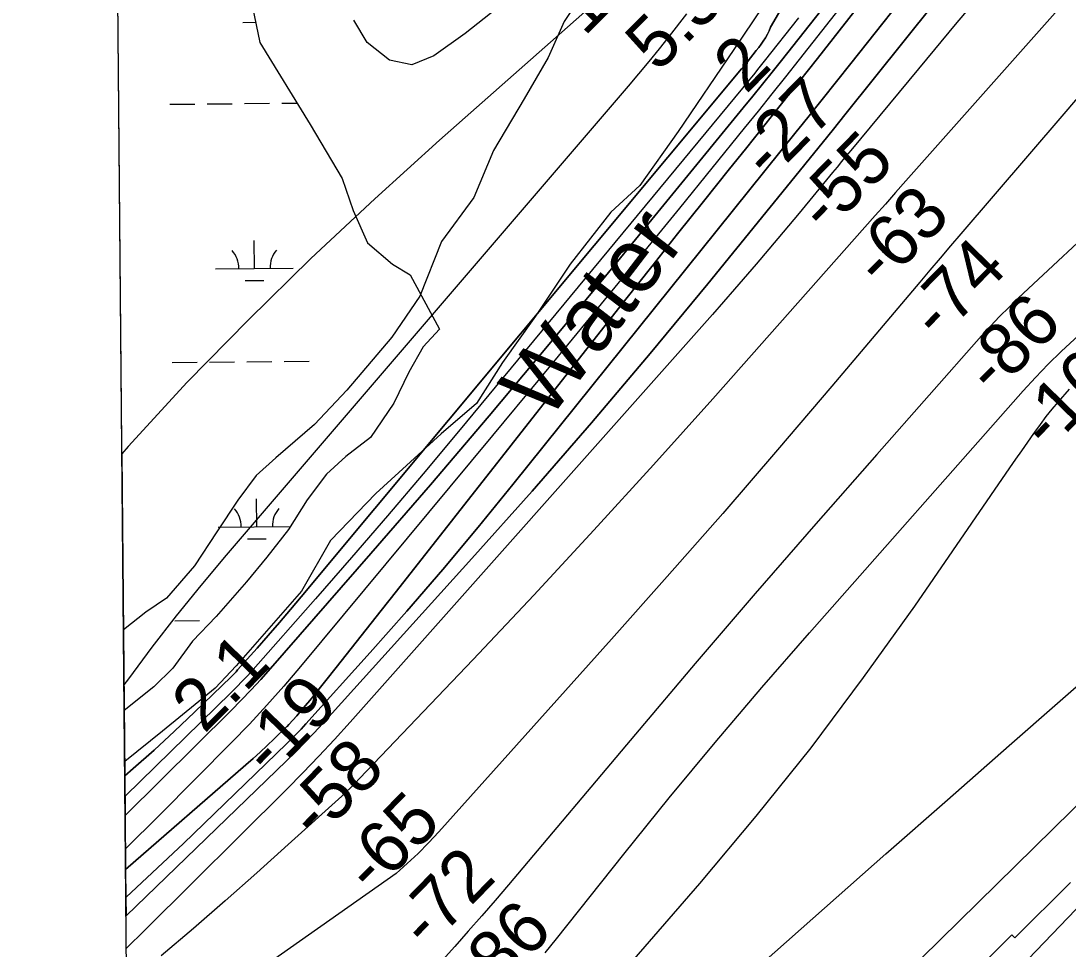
# Model space of a CAD drawing. Extents: x 3598634 to 3636690, y 517270 to 542944.
# Drawn here: x 3602690 to 3604038, y 525564 to 526759 of the extents above; entities that cross this region are included whole.
import ezdxf

# ---------------------------------------------------------------- set-up
doc = ezdxf.new("R2010")
doc.units = 0
for name, color, linetype in [('V-GRID-FRAM', 7, 'Continuous'), ('V-RIVR-EDGE', 7, 'Continuous'), ('V-RIVR-IDEN', 7, 'Continuous'), ('V-RIVR-RANG', 7, 'Continuous'), ('V-RRAP-RVMT', 7, 'Continuous'), ('V-SITE-VEGE', 7, 'Continuous'), ('V-TOPO-DPTH', 7, 'Continuous'), ('V-TOPO-MAJR', 7, 'Continuous'), ('V-TOPO-MINR', 7, 'Continuous'), ('V-TOPO-WATR', 7, 'Continuous'), ('V-WETL-SWMP', 7, 'Continuous')]:
    doc.layers.add(name, color=color, linetype=linetype)

msp = doc.modelspace()

# ---------------------------------------------------------------- linework, layer by layer
at = {"layer": 'V-GRID-FRAM'}
msp.add_lwpolyline([(3602690.3, 540859.2), (3634347.4, 541153.9), (3634524.6, 522971.8), (3602851.6, 522676.9), (3602690.3, 540859.2)], dxfattribs=at)
at = {"layer": 'V-RIVR-EDGE'}
msp.add_lwpolyline([(3603689.5, 526840.5), (3603658.1, 526797), (3603608.3, 526722.4), (3603536.4, 526617.2), (3603487.2, 526547.5), (3603449.7, 526513.3), (3603397.5, 526446), (3603352.6, 526379.3), (3603310.1, 526319.4), (3603276.9, 526266.8), (3603231.5, 526227.7), (3603147.4, 526150.7), (3603089, 526090.1), (3603051.5, 526024.7), (3602967.3, 525928.7), (3602940.2, 525900), (3602872.7, 525844.4), (3602823.9, 525805.3)], dxfattribs=at)
at = {"layer": 'V-RRAP-RVMT'}
for p, q in [((3604041.5, 525649.8), (3603970.1, 525578.4)), ((3603966.1, 525582.3), (3603878.4, 525494.7)), ((3603970.1, 525578.4), (3603966.1, 525582.3))]:
    msp.add_line(p, q, dxfattribs=at)
at = {"layer": 'V-SITE-VEGE'}
for p, q in [((3602822.4, 525975.2), (3602813.5, 526979.6)), ((3603424.1, 526810.7), (3603389.8, 526758.5)), ((3603389.8, 526758.5), (3603369.3, 526712.1)), ((3603369.3, 526712.1), (3603338.2, 526659.2)), ((3603338.2, 526659.2), (3603298.9, 526592.4)), ((3603298.9, 526592.4), (3603273.5, 526532.1)), ((3603273.5, 526532.1), (3603231.8, 526475.1)), ((3603231.8, 526475.1), (3603204, 526405)), ((3603204, 526405), (3603168, 526352.1)), ((3603168, 526352.1), (3603109.9, 526283.7)), ((3603109.9, 526283.7), (3603068.3, 526239.8)), ((3603068.3, 526239.8), (3603018.5, 526196.7)), ((3603018.5, 526196.7), (3602993.1, 526173.9)), ((3602993.1, 526173.9), (3602969.4, 526142.1)), ((3602969.4, 526142.1), (3602942.4, 526101.4)), ((3602942.4, 526101.4), (3602913.8, 526057.4)), ((3602913.8, 526057.4), (3602877.8, 526015.9)), ((3602877.8, 526015.9), (3602850.9, 525998)), ((3602850.9, 525998), (3602822.4, 525975.2))]:
    msp.add_line(p, q, dxfattribs=at)
at = {"layer": 'V-TOPO-DPTH'}
for points in [[(3604119.6, 527546.6), (3603655.5, 526751.3), (3603653.6, 526746.6), (3603651.3, 526742.2), (3603648.8, 526737.8), (3603646.1, 526733.5), (3603643.2, 526729.3), (3603640.2, 526725.2), (3603637.1, 526721.2), (3603625.4, 526706.4), (3603623.6, 526704.2), (3603621.8, 526702), (3603620, 526699.8), (3603618.2, 526697.7), (3603051.3, 526017.8), (3603037.2, 526001.1), (3603023, 525984.4), (3603008.7, 525967.9), (3602994.3, 525951.5), (3602969.3, 525923.4), (3602967.3, 525921.2), (3602965.2, 525918.9), (3602963, 525916.7), (3602960.8, 525914.6), (3602913.9, 525869), (3602887.9, 525844.4), (3602861.7, 525820.2), (3602834.8, 525796.5), (3602824, 525787.2), (3602824.5, 525736)], [(3602824, 525787.2), (3602834.8, 525796.5), (3602861.7, 525820.2), (3602887.9, 525844.4), (3602913.9, 525869), (3602960.8, 525914.6), (3602963, 525916.7), (3602965.2, 525918.9), (3602967.3, 525921.2), (3602969.3, 525923.4), (3602994.3, 525951.5), (3603008.7, 525967.9), (3603023, 525984.4), (3603037.2, 526001.1), (3603051.3, 526017.8), (3603618.2, 526697.7), (3603620, 526699.8), (3603621.8, 526702), (3603623.6, 526704.2), (3603625.4, 526706.4), (3603637.1, 526721.2), (3603640.2, 526725.2), (3603643.2, 526729.3), (3603646.1, 526733.5), (3603648.8, 526737.8), (3603651.3, 526742.2), (3603653.6, 526746.6), (3603655.5, 526751.3), (3604119.6, 527546.6)], [(3602825.4, 525630.2), (3602825.6, 525606.7), (3603032.1, 525806.3), (3603044.1, 525818.1), (3603055.8, 525830), (3603067.4, 525842.2), (3603078.8, 525854.5), (3603270.8, 526066.8), (3603348.4, 526153.9), (3603425, 526241.8), (3603500.3, 526330.9), (3603574.6, 526420.8), (3603692.1, 526565.3), (3603706.9, 526583.6), (3603721.7, 526601.9), (3603736.5, 526620.2), (3603751.2, 526638.6), (3604205.8, 527206.3)], [(3604205.8, 527206.3), (3603751.2, 526638.6), (3603736.5, 526620.2), (3603721.7, 526601.9), (3603706.9, 526583.6), (3603692.1, 526565.3), (3603574.6, 526420.8), (3603500.3, 526330.9), (3603425, 526241.8), (3603348.4, 526153.9), (3603270.8, 526066.8), (3603078.8, 525854.5), (3603067.4, 525842.2), (3603055.8, 525830), (3603044.1, 525818.1), (3603032.1, 525806.3), (3602825.6, 525606.7)], [(3602824.5, 525736), (3602825.1, 525666.4), (3602979.9, 525801.3), (3602989.1, 525809.5), (3602998.2, 525817.7), (3603007.2, 525826.1), (3603016.2, 525834.5), (3603032.3, 525850.1), (3603033, 525850.8), (3603035.3, 525853.2), (3603045.4, 525864.5), (3603051.2, 525871), (3603056.8, 525877.6), (3603062.4, 525884.2), (3603067.8, 525891), (3603096, 525926.5), (3603115.5, 525951), (3603134.9, 525975.6), (3603154.3, 526000.2), (3603173.7, 526024.8), (3603469.3, 526401.1), (3603502.5, 526443.2), (3603535.7, 526485.2), (3603569.1, 526527), (3603602.6, 526568.8), (3603623, 526594.1), (3603646.3, 526623.3), (3603669.5, 526652.5), (3603692.6, 526681.7), (3603715.7, 526711.1), (3603832.3, 526860.2)], [(3603832.3, 526860.2), (3603715.7, 526711.1), (3603692.6, 526681.7), (3603669.5, 526652.5), (3603646.3, 526623.3), (3603623, 526594.1), (3603602.6, 526568.8), (3603569.1, 526527), (3603535.7, 526485.2), (3603502.5, 526443.2), (3603469.3, 526401.1), (3603173.7, 526024.8), (3603154.3, 526000.2), (3603134.9, 525975.6), (3603115.5, 525951), (3603096, 525926.5), (3603067.8, 525891), (3603062.4, 525884.2), (3603056.8, 525877.6), (3603051.2, 525871), (3603045.4, 525864.5), (3603035.3, 525853.2), (3603033, 525850.8), (3603032.3, 525850.1), (3603016.2, 525834.5), (3603007.2, 525826.1), (3602998.2, 525817.7), (3602989.1, 525809.5), (3602979.9, 525801.3), (3602825.1, 525666.4)], [(3603474.8, 526823.2), (3603229.2, 526605.8), (3603145.8, 526530.2), (3603063.6, 526453.2), (3602983.3, 526374.3), (3602904.3, 526294.1), (3602828.4, 526211.1), (3602820.4, 526201.7), (3602824, 525787.2)], [(3603742.5, 526801.2), (3603669.5, 526708.6), (3603657.3, 526693.2), (3603645, 526677.9), (3603632.7, 526662.6), (3603620.3, 526647.4), (3603442.8, 526430.6), (3603368.3, 526340.5), (3603293.2, 526250.9), (3603217.4, 526162), (3603140.9, 526073.5), (3603011.5, 525925.1), (3602999.2, 525911.3), (3602986.7, 525897.8), (3602974, 525884.4), (3602961, 525871.3), (3602824.5, 525736)], [(3602824.5, 525736), (3602961, 525871.3), (3602974, 525884.4), (3602986.7, 525897.8), (3602999.2, 525911.3), (3603011.5, 525925.1), (3603140.9, 526073.5), (3603217.4, 526162), (3603293.2, 526250.9), (3603368.3, 526340.5), (3603442.8, 526430.6), (3603620.3, 526647.4), (3603632.7, 526662.6), (3603645, 526677.9), (3603657.3, 526693.2), (3603669.5, 526708.6), (3603742.5, 526801.2)], [(3602825.1, 525666.4), (3602825.4, 525630.2), (3602825.9, 525630.6), (3602899.4, 525700.1), (3603032.2, 525828.2), (3603038.5, 525834.5), (3603044.8, 525840.8), (3603051, 525847.3), (3603057, 525853.9), (3603140, 525946), (3603187, 525999.1), (3603233.4, 526052.8), (3603278.9, 526107.2), (3603323.7, 526162.1), (3603688.6, 526616.7), (3603692.3, 526621.3), (3603696, 526625.9), (3603699.7, 526630.5), (3603703.3, 526635.2), (3603758.9, 526704.7), (3603790.3, 526744.2), (3603821.6, 526783.7)], [(3603821.6, 526783.7), (3603790.3, 526744.2), (3603758.9, 526704.7), (3603703.3, 526635.2), (3603699.7, 526630.5), (3603696, 526625.9), (3603692.3, 526621.3), (3603688.6, 526616.7), (3603323.7, 526162.1), (3603278.9, 526107.2), (3603233.4, 526052.8), (3603187, 525999.1), (3603140, 525946), (3603057, 525853.9), (3603051, 525847.3), (3603044.8, 525840.8), (3603038.5, 525834.5), (3603032.2, 525828.2), (3602899.4, 525700.1), (3602825.9, 525630.6), (3602825.4, 525630.2)]]:
    msp.add_lwpolyline(points, dxfattribs=at)
at = {"layer": 'V-TOPO-MAJR'}
for points in [[(3603945.4, 526816.6), (3603895.4, 526757.4), (3603845.8, 526697.8), (3603758.7, 526592.6), (3603752.8, 526585.5), (3603746.9, 526578.3), (3603741.1, 526571.2), (3603735.2, 526564.1), (3603692.3, 526512), (3603664.9, 526479), (3603637.1, 526446.2), (3603609, 526413.7), (3603580.7, 526381.4), (3603114, 525856), (3603094.1, 525834), (3603074, 525812.2), (3603053.4, 525790.9), (3603032.6, 525769.8), (3602850.3, 525588.5), (3602826, 525564.7)], [(3603440.5, 525505.2), (3603564.3, 525648.2), (3603636.9, 525734.9), (3603707.6, 525823.2), (3603775.3, 525913.7), (3603841.1, 526005.8), (3603963.7, 526183.7), (3603971.4, 526194.8), (3603979, 526205.8), (3603986.7, 526216.9), (3603994.4, 526228), (3603995.5, 526229.6), (3604002.8, 526239.7), (3604010.3, 526249.7), (3604018.2, 526259.4), (3604026.2, 526268.9), (3604040.2, 526284.9)]]:
    msp.add_lwpolyline(points, dxfattribs=at)
at = {"layer": 'V-TOPO-MINR'}
for points in [[(3604205.8, 527206.3), (3603751.2, 526638.6), (3603736.5, 526620.2), (3603721.7, 526601.9), (3603706.9, 526583.6), (3603692.1, 526565.3), (3603574.6, 526420.8), (3603500.3, 526330.9), (3603425, 526241.8), (3603348.4, 526153.9), (3603270.8, 526066.8), (3603078.8, 525854.5), (3603067.4, 525842.2), (3603055.8, 525830), (3603044.1, 525818.1), (3603032.1, 525806.3), (3602825.6, 525606.7)], [(3603365.2, 525559), (3603379.7, 525577), (3603466.6, 525686.3), (3603525, 525758.6), (3603584.1, 525830.2), (3603644.4, 525901), (3603705.4, 525971.1), (3603980.8, 526282.8), (3603996.7, 526300.1), (3604012.9, 526317.1), (3604029.7, 526333.5), (3604046.8, 526349.6), (3604189.4, 526478.6), (3604271.1, 526550.5), (3604354.2, 526620.8), (3604439.2, 526688.7), (3604525.5, 526755.1), (3604676.3, 526867.6)], [(3603832.3, 526860.2), (3603715.7, 526711.1), (3603692.6, 526681.7), (3603669.5, 526652.5), (3603646.3, 526623.3), (3603623, 526594.1), (3603602.6, 526568.8), (3603569.1, 526527), (3603535.7, 526485.2), (3603502.5, 526443.2), (3603469.3, 526401.1), (3603173.7, 526024.8), (3603154.3, 526000.2), (3603134.9, 525975.6), (3603115.5, 525951), (3603096, 525926.5), (3603067.8, 525891), (3603062.4, 525884.2), (3603056.8, 525877.6), (3603051.2, 525871), (3603045.4, 525864.5), (3603035.3, 525853.2), (3603033, 525850.8), (3603032.3, 525850.1), (3603016.2, 525834.5), (3603007.2, 525826.1), (3602998.2, 525817.7), (3602989.1, 525809.5), (3602979.9, 525801.3), (3602825.1, 525666.4)], [(3603789.8, 526834), (3603692.3, 526709.8), (3603674.7, 526687.5), (3603657.1, 526665.4), (3603639.4, 526643.3), (3603621.6, 526621.2), (3603538, 526518.1), (3603478.2, 526444.7), (3603418.2, 526371.4), (3603358, 526298.3), (3603297.6, 526225.4), (3603050.1, 525927.7), (3603028.7, 525902.6), (3603006.9, 525877.9), (3602984.4, 525853.8), (3602961.6, 525830.1), (3602868.8, 525736.4), (3602824.9, 525692.9)], [(3603474.8, 526823.2), (3603229.2, 526605.8), (3603145.8, 526530.2), (3603063.6, 526453.2), (3602983.3, 526374.3), (3602904.3, 526294.1), (3602828.4, 526211.1), (3602820.4, 526201.7)], [(3604186.6, 526819.7), (3604108.5, 526728.2), (3604030.3, 526636.8), (3603900.4, 526485.1), (3603887.1, 526469.6), (3603873.9, 526454), (3603860.7, 526438.4), (3603847.5, 526422.8), (3603734.4, 526289), (3603664.3, 526206.8), (3603593.8, 526125), (3603522.5, 526043.9), (3603450.8, 525963.1), (3603228.2, 525714.8), (3603215.1, 525700.8), (3603201.7, 525687.1), (3603187.7, 525674), (3603173.3, 525661.2), (3602827.3, 525417.7)], [(3603742.5, 526801.2), (3603669.5, 526708.6), (3603657.3, 526693.2), (3603645, 526677.9), (3603632.7, 526662.6), (3603620.3, 526647.4), (3603442.8, 526430.6), (3603368.3, 526340.5), (3603293.2, 526250.9), (3603217.4, 526162), (3603140.9, 526073.5), (3603011.5, 525925.1), (3602999.2, 525911.3), (3602986.7, 525897.8), (3602974, 525884.4), (3602961, 525871.3), (3602824.5, 525736)], [(3603821.6, 526783.7), (3603790.3, 526744.2), (3603758.9, 526704.7), (3603703.3, 526635.2), (3603699.7, 526630.5), (3603696, 526625.9), (3603692.3, 526621.3), (3603688.6, 526616.7), (3603323.7, 526162.1), (3603278.9, 526107.2), (3603233.4, 526052.8), (3603187, 525999.1), (3603140, 525946), (3603057, 525853.9), (3603051, 525847.3), (3603044.8, 525840.8), (3603038.5, 525834.5), (3603032.2, 525828.2), (3602899.4, 525700.1), (3602825.9, 525630.6), (3602825.4, 525630.2)], [(3604035.4, 526785.1), (3603829.8, 526553.3), (3603816.5, 526538.4), (3603803.3, 526523.5), (3603790.1, 526508.6), (3603776.8, 526493.7), (3603580.9, 526272.7), (3603504.8, 526187.8), (3603428.1, 526103.4), (3603350.6, 526019.9), (3603272.4, 525937), (3603126.3, 525783.5), (3603120.7, 525777.8), (3603115, 525772.1), (3603109.2, 525766.5), (3603103.3, 525761), (3603034.5, 525698.7), (3602994.1, 525662.3), (3602953.3, 525626.2), (3602912.3, 525590.4), (3602871, 525555)], [(3604398.5, 526772.4), (3604320.5, 526710.8), (3604243.7, 526647.6), (3604168.8, 526582.2), (3604095.1, 526515.3), (3603974.8, 526402.7), (3603962.5, 526390.8), (3603950.3, 526378.7), (3603938.6, 526366.3), (3603927, 526353.6), (3603792.2, 526201.1), (3603713.7, 526111.7), (3603635.7, 526021.9), (3603558.3, 525931.6), (3603481.4, 525840.9), (3603317.9, 525646.5), (3603300.8, 525626.5), (3603283.7, 525606.6), (3603266.3, 525586.9), (3603248.9, 525567.3), (3603163.5, 525472.5)], [(3603547.2, 526768.4), (3603524.8, 526739.8), (3603511.9, 526723.5), (3603498.8, 526707.3), (3603485.5, 526691.3), (3603472.1, 526675.4), (3602954.4, 526071.3), (3602921.9, 526032.4), (3602890, 525993), (3602859, 525952.8), (3602828.7, 525912.1), (3602823, 525904.3)], [(3603691.4, 526763.3), (3603647.2, 526707.5), (3603640.3, 526698.8), (3603633.3, 526690.1), (3603626.3, 526681.4), (3603619.2, 526672.8), (3603253.6, 526230.5), (3603208.2, 526176.1), (3603162.4, 526122), (3603116.1, 526068.3), (3603069.4, 526015), (3602989.2, 525924.2), (3602982.3, 525916.5), (3602975.3, 525909), (3602968.1, 525901.6), (3602960.8, 525894.3), (3602824.3, 525760.7)], [(3603645.9, 525546.6), (3603724.9, 525616.6), (3603804, 525686.5), (3603883.2, 525756.3), (3603962.5, 525826), (3604221.7, 526053.3), (3604237.3, 526067), (3604252.9, 526080.8), (3604268.4, 526094.7), (3604283.9, 526108.5), (3604299.3, 526122.4), (3604314.8, 526136.2), (3604330.4, 526150), (3604346, 526163.8), (3604446.1, 526252), (3604511.9, 526309.6), (3604577.9, 526367), (3604644.3, 526424), (3604710.8, 526480.7), (3604835, 526585.8)], [(3603728.8, 525433.1), (3604310, 526004.4), (3604315.1, 526009.4), (3604320.3, 526014.4), (3604325.6, 526019.3), (3604330.9, 526024.1), (3604370.5, 526059.6), (3604395.8, 526081.9), (3604421.4, 526103.8), (3604447.5, 526125.3), (3604473.8, 526146.4), (3604482.5, 526153.2), (3604513.6, 526177.3), (3604544.9, 526201.1), (3604576.5, 526224.4), (3604608.3, 526247.5), (3604771.9, 526364.5), (3604796.2, 526379.8), (3604821.4, 526393), (3604848, 526403.2)], [(3603702.1, 525254), (3604354.1, 525933.5)]]:
    msp.add_lwpolyline(points, dxfattribs=at)
at = {"layer": 'V-TOPO-WATR'}
msp.add_lwpolyline([(3604119.6, 527546.6), (3603655.5, 526751.3), (3603653.6, 526746.6), (3603651.3, 526742.2), (3603648.8, 526737.8), (3603646.1, 526733.5), (3603643.2, 526729.3), (3603640.2, 526725.2), (3603637.1, 526721.2), (3603625.4, 526706.4), (3603623.6, 526704.2), (3603621.8, 526702), (3603620, 526699.8), (3603618.2, 526697.7), (3603051.3, 526017.8), (3603037.2, 526001.1), (3603023, 525984.4), (3603008.7, 525967.9), (3602994.3, 525951.5), (3602969.3, 525923.4), (3602967.3, 525921.2), (3602965.2, 525918.9), (3602963, 525916.7), (3602960.8, 525914.6), (3602913.9, 525869), (3602887.9, 525844.4), (3602861.7, 525820.2), (3602834.8, 525796.5), (3602824, 525787.2)], dxfattribs=at)
at = {"layer": 'V-WETL-SWMP'}
for p, q in [((3602823.3, 525871.2), (3602813.4, 526990.4)), ((3602979.6, 526819.4), (3602998, 526731.8)), ((3602976, 526757.6), (3602992.6, 526757.8)), ((3602998, 526731.8), (3603062.6, 526625.8)), ((3602882.2, 526652.1), (3602914.2, 526652.4)), ((3602930.2, 526652.5), (3602962.2, 526652.8)), ((3602978.2, 526653), (3603010.2, 526653.3)), ((3603026.2, 526653.4), (3603045.6, 526653.6)), ((3603062.6, 526625.8), (3603104.1, 526556.6)), ((3603104.1, 526556.6), (3603117.9, 526515.1)), ((3603117.9, 526515.1), (3603136.3, 526473.6)), ((3602991, 526440.5), (3602990.6, 526476.5)), ((3603136.3, 526473.6), (3603168.6, 526446)), ((3602941, 526440), (3603041, 526441)), ((3603168.6, 526446), (3603191.6, 526432.2)), ((3602979.1, 526425), (3603003.1, 526425.2)), ((3603191.6, 526432.2), (3603229.3, 526362.3)), ((3603229.3, 526362.3), (3603208, 526339.7)), ((3603208, 526339.7), (3603189.9, 526307.1)), ((3602885.2, 526319.4), (3602917.2, 526319.7)), ((3602933.2, 526319.9), (3602965.2, 526320.2)), ((3602981.2, 526320.3), (3603013.2, 526320.6)), ((3603029.2, 526320.8), (3603061.2, 526321.1)), ((3603189.9, 526307.1), (3603170.5, 526267)), ((3603170.5, 526267), (3603140.2, 526222.8)), ((3603140.2, 526222.8), (3603108.4, 526198.3)), ((3603108.4, 526198.3), (3603083.8, 526175.8)), ((3603083.8, 526175.8), (3603058.8, 526142.5)), ((3602994.1, 526107.8), (3602993.7, 526143.8)), ((3603058.8, 526142.5), (3603035, 526104.4)), ((3602944.1, 526107.4), (3603037.5, 526108.2)), ((3603035, 526104.4), (3603006.8, 526068.6)), ((3602982.2, 526092.3), (3603006.2, 526092.5)), ((3603006.8, 526068.6), (3602980.6, 526036.9)), ((3602980.6, 526036.9), (3602941.5, 525992.4)), ((3602941.5, 525992.4), (3602911.3, 525960.6)), ((3602888.3, 525986.8), (3602920.3, 525987.1)), ((3602936.3, 525987.2), (3602936.6, 525987.2)), ((3602911.3, 525960.6), (3602885.9, 525925.7)), ((3602885.9, 525925.7), (3602861.3, 525901.6)), ((3602861.3, 525901.6), (3602823.3, 525871.2))]:
    msp.add_line(p, q, dxfattribs=at)
msp.add_lwpolyline([(3603319.3, 526788.9), (3603262.1, 526743.1), (3603222, 526714.5), (3603193.4, 526703), (3603164.7, 526708.7), (3603136.1, 526731.6), (3603118.9, 526760.3)], dxfattribs=at)
for centre, start, end in [((3602935.7, 526440.5), 359.7615, 41.3052), ((3603046.2, 526441.5), 139.7615, 181.3052), ((3602938.8, 526107.8), 359.7615, 41.3052), ((3603049.3, 526108.8), 139.7615, 181.3052)]:
    msp.add_arc(centre, 35.2, start, end, dxfattribs=at)

# ---------------------------------------------------------------- texts
at = {"layer": 'V-RIVR-IDEN'}
msp.add_text('Water', height=83, rotation=52.5606, dxfattribs=at).set_placement((3603368.1, 526241.8))
at = {"layer": 'V-RIVR-RANG'}
for s, rotation, p in [('12.4', 45.2983, (3603415.8, 526738.4)), ('5.3', 45.2983, (3603510.4, 526691.9)), ('2', 45.5823, (3603624, 526664.3)), ('-27', 45.5823, (3603654.2, 526552.3)), ('-55', 45.5823, (3603727, 526483.7)), ('-63', 45.5823, (3603798.6, 526413.9)), ('-74', 45.5823, (3603871.9, 526345.8)), ('-86', 45.5823, (3603942.6, 526275.1)), ('-101', 45.5823, (3604012.9, 526203.9)), ('2.1', 45.4283, (3602926.4, 525840.4)), ('-19', 45.7106, (3603011.3, 525783.7)), ('-58', 45.7106, (3603071.1, 525701.8)), ('-65', 45.7106, (3603143.3, 525632.5)), ('-72', 45.7106, (3603213.6, 525561.4)), ('-86', 45.7106, (3603286.4, 525492.9))]:
    msp.add_text(s, height=67, rotation=rotation, dxfattribs=at).set_placement(p)

doc.saveas('drawing.dxf')
